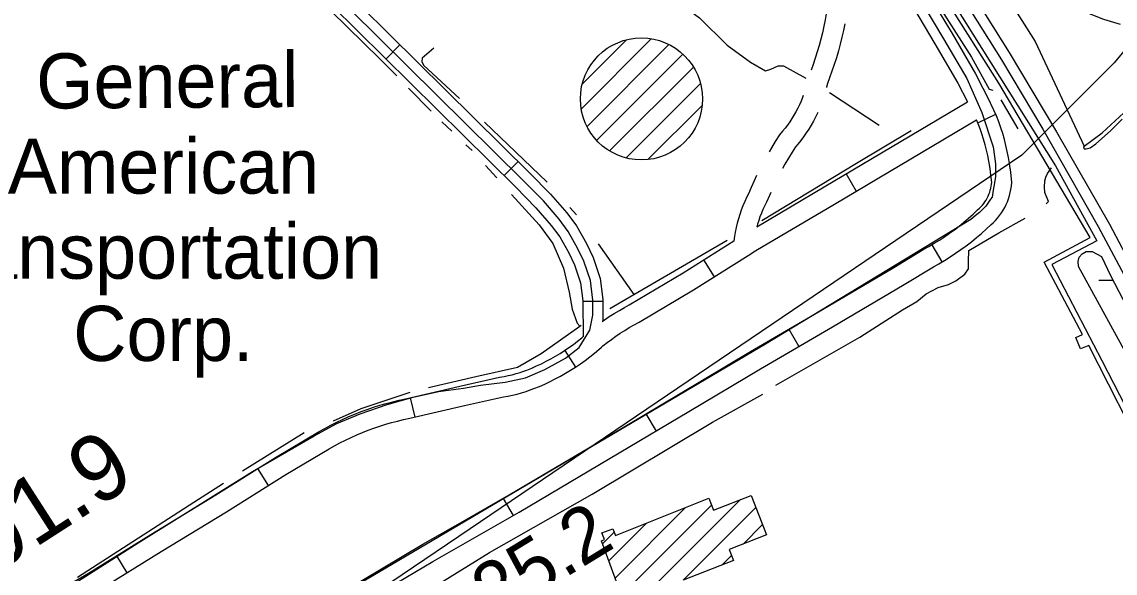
# Model space of a CAD drawing. Extents: x 3568792 to 3606828, y 529143 to 554785.
# Drawn here: x 3577857 to 3579503, y 542432 to 543262 of the extents above; entities that cross this region are included whole.
import ezdxf

# ---------------------------------------------------------------- set-up
doc = ezdxf.new("R2010")
doc.units = 0
for name, color, linetype in [('V-BLDG-IDEN', 7, 'Continuous'), ('V-BLDG-OTLN', 7, 'Continuous'), ('V-DOMW-TANK', 7, 'Continuous'), ('V-RAIL-TRAK', 7, 'Continuous'), ('V-RIVR-RANG-IDEN', 7, 'Continuous'), ('V-ROAD-CNTR', 7, 'Continuous'), ('V-SITE-OTLN', 7, 'Continuous'), ('V-SURV-IDEN', 7, 'Continuous'), ('V-TOPO-SHOR', 7, 'Continuous'), ('V-UTIL-LINE', 7, 'Continuous'), ('V-WETL-SWMP', 7, 'Continuous')]:
    doc.layers.add(name, color=color, linetype=linetype)

msp = doc.modelspace()

# ---------------------------------------------------------------- linework, layer by layer
at = {"layer": 'V-BLDG-OTLN'}
for p, q in [((3578815.2, 542419.2), (3578939.2, 542543.2)), ((3578750.4, 542425.1), (3578856.6, 542531.3)), ((3578759.9, 542399.3), (3578895.7, 542535)), ((3578853.2, 542421.8), (3578962.5, 542531.1)), ((3578741, 542451), (3578797.6, 542507.6)), ((3578731.5, 542476.8), (3578748.9, 542494.3)), ((3578943.1, 542476.3), (3578972.5, 542505.7)), ((3578911.6, 542444.9), (3578925.6, 542458.9))]:
    msp.add_line(p, q, dxfattribs=at)
msp.add_lwpolyline([(3578760.1, 542398.9), (3578729.8, 542481.3), (3578734.5, 542483), (3578730.7, 542493.1), (3578747.1, 542499.2), (3578750.9, 542488.9), (3578891.6, 542545.3), (3578898.8, 542527.3), (3578955.3, 542549.5), (3578978.5, 542490.2), (3578922, 542468.1), (3578928.5, 542451.5), (3578853.1, 542421.8)], dxfattribs=at)
at = {"layer": 'V-DOMW-TANK'}
for p, q in [((3578699.7, 543131.7), (3578804.8, 543236.8)), ((3578701, 543168.4), (3578767.9, 543235.3)), ((3578708.3, 543105), (3578831.5, 543228.2)), ((3578722.9, 543084.2), (3578852.4, 543213.7)), ((3578742.3, 543068.2), (3578868.3, 543194.3)), ((3578767.1, 543057.7), (3578878.9, 543169.5)), ((3578799.7, 543055), (3578881.4, 543136.6))]:
    msp.add_line(p, q, dxfattribs=at)
msp.add_circle((3578790.2, 543146.4), 91.9, dxfattribs=at)
at = {"layer": 'V-RAIL-TRAK'}
for points in [[(3578536.4, 544224.4), (3578627.1, 544129.6), (3578694.9, 544054.9), (3578778.3, 543960.5), (3578866.7, 543856.9), (3578955.1, 543745.6), (3579031.6, 543647.5), (3579088.4, 543571.9), (3579177.7, 543441.8), (3579267.5, 543308.4), (3579332.1, 543205.3), (3579394.4, 543100.9), (3579477.7, 542954.3), (3579574.8, 542772.3)], [(3578565.7, 544214.1), (3578656.6, 544118.2), (3578746.6, 544020.4), (3578839.8, 543911.9), (3578933, 543799.6), (3579019.3, 543688.8), (3579105.3, 543574.3), (3579173.6, 543478.4), (3579272.6, 543330), (3579343.6, 543216.4), (3579415.1, 543096.9), (3579494.7, 542958), (3579566.2, 542822.8)]]:
    msp.add_lwpolyline(points, dxfattribs=at)
at = {"layer": 'V-ROAD-CNTR'}
for p, q in [((3578426.8, 543228.2), (3578405.7, 543206.8)), ((3579296.5, 543110.5), (3579323.5, 543123.5)), ((3578604.5, 543052.4), (3578583.4, 543031)), ((3579098.1, 543033.4), (3579113.5, 543007.6)), ((3579227.3, 542926.9), (3579242.5, 542901)), ((3578883.8, 542903.9), (3578899.8, 542878.6)), ((3578732, 542841.6), (3578702, 542841.4)), ((3579012.1, 542799.8), (3579027.2, 542773.9)), ((3578674.6, 542767.7), (3578690.8, 542742.4)), ((3578442, 542696.6), (3578448.8, 542667.4)), ((3578797, 542672.3), (3578812.2, 542646.4)), ((3578212.3, 542589.9), (3578228.3, 542564.4)), ((3578582, 542545), (3578596.9, 542519)), ((3577999.8, 542458.4), (3578015.5, 542432.9))]:
    msp.add_line(p, q, dxfattribs=at)
for points in [[(3578663.5, 544023.6), (3578672.4, 544020), (3578747.8, 543935.9), (3578841.6, 543826.5), (3578906.9, 543744), (3578989.7, 543635.9), (3579078.1, 543516.5), (3579159.4, 543395.7), (3579225, 543299.6), (3579257.8, 543244.7), (3579293.1, 543184), (3579315.1, 543141)], [(3578025, 543584.3), (3578125.4, 543484), (3578601, 543013.7), (3578631.4, 542982.6), (3578654.5, 542955.9), (3578667.2, 542938.7), (3578680.8, 542914.5), (3578689.6, 542896.4), (3578698.6, 542869.5), (3578701.9, 542842.4), (3578702.3, 542788.2)], [(3577653.3, 542236.7), (3578032.5, 542478.2), (3578204.9, 542585.6), (3578297.7, 542639.2), (3578331.4, 542657.9), (3578366.7, 542672.5), (3578407.5, 542686.3), (3578446.6, 542697.2), (3578484.8, 542705.7), (3578522.2, 542711), (3578547.9, 542715.4), (3578585.2, 542720.2), (3578615.5, 542726.7), (3578644.7, 542739.2), (3578675.7, 542756), (3578696.3, 542772), (3578712.5, 542798.2), (3578717, 542820.9), (3578716.9, 542843.4), (3578713.3, 542872.8), (3578703.6, 542902.1), (3578694.1, 542921.5), (3578679.8, 542946.9), (3578666.2, 542965.3), (3578642.5, 542992.8), (3578611.6, 543024.3), (3578136, 543494.6)], [(3578157.2, 543494.8), (3578622.3, 543034.8), (3578653.5, 543002.9), (3578677.9, 542974.7), (3578692.5, 542955.1), (3578707.4, 542928.5), (3578717.5, 542907.7), (3578728, 542876.1), (3578731.9, 542844.3), (3578732.1, 542812.8)], [(3579140.1, 543370.7), (3579199.8, 543283.4), (3579231.9, 543229.5), (3579266.4, 543170.2), (3579280.8, 543142.1)], [(3579212.4, 543291.5), (3579244.8, 543237.1), (3579279.8, 543177.1), (3579302.7, 543126.1), (3579319.6, 543074.1), (3579323.1, 543048.9), (3579323.2, 543029.6), (3579321.6, 543020.2), (3579319.5, 543008.9), (3579317.9, 542998.6), (3579315.7, 542995.7), (3579308.5, 542984.7), (3579299.3, 542975.5), (3579295.2, 542972.2), (3579286, 542964.9), (3578977, 542777.3), (3578305.2, 542380.6)], [(3579070.4, 543286.6), (3579066.8, 543265.6), (3579064.9, 543255.9), (3579062.7, 543246.1), (3579060.3, 543236.5), (3579057.7, 543226.8), (3579054.9, 543217.2), (3579051.9, 543207.7), (3579048.7, 543198.3), (3579045.6, 543189.9)], [(3579096.2, 543259.5), (3579094.2, 543249.6), (3579091.9, 543239.3), (3579089.3, 543229), (3579086.6, 543218.7), (3579083.6, 543208.5), (3579080.4, 543198.4), (3579077, 543188.3), (3579073.3, 543178.3), (3579070, 543169.6), (3579068.8, 543164.2), (3579068.6, 543163.6)], [(3579033.8, 543151.8), (3579032.6, 543148.6), (3579030.4, 543143.1), (3579028, 543137.7), (3579025.4, 543132.4), (3579022.7, 543127.1), (3579019.7, 543122), (3579016.6, 543116.9), (3579013.4, 543112), (3579010, 543107.1), (3579006.4, 543102.4), (3579002.7, 543097.8), (3578997.9, 543092.3), (3578991.4, 543082.1), (3578985.7, 543072.6), (3578982.2, 543066.6)], [(3578354.3, 542377.6), (3578476.3, 542450), (3578539.6, 542486.2), (3578606.2, 542524.2), (3578756.7, 542613.6), (3578861.5, 542675.6), (3578969.5, 542740.2), (3579077.9, 542803.5), (3579185.6, 542866.9), (3579229.7, 542893.7), (3579237.9, 542898.3), (3579246.4, 542903.3), (3579254.8, 542908.6), (3579263, 542914), (3579271.1, 542919.6), (3579279.1, 542925.4), (3579287, 542931.4), (3579294.7, 542937.7), (3579302.2, 542944), (3579309.6, 542950.6), (3579316.6, 542957.1), (3579319.8, 542960), (3579323.1, 542963.4), (3579326.3, 542967), (3579329.3, 542970.8), (3579332.1, 542974.7), (3579334.7, 542978.8), (3579337.1, 542982.9), (3579339.2, 542987.3), (3579341.1, 542991.7), (3579342.8, 542996.2), (3579344.2, 543000.8), (3579345.4, 543005.4), (3579346.3, 543010.1), (3579347, 543014.9), (3579347.5, 543020.6), (3579346.6, 543030.9), (3579345.5, 543040.1), (3579345.2, 543041.9), (3579344.2, 543049.2), (3579342.6, 543058.3), (3579340.8, 543067.4), (3579338.8, 543076.4), (3579336.5, 543085.3), (3579334, 543094.2), (3579331.2, 543103), (3579328.2, 543111.7), (3579324.8, 543120.8), (3579316.6, 543137.9), (3579315.1, 543141)], [(3578963.8, 542953.7), (3579065.4, 543013.9), (3579280.8, 543142.1)], [(3579055.5, 543125.8), (3579055.2, 543125.1), (3579052.2, 543118.9), (3579049, 543112.8), (3579045.6, 543106.8), (3579042, 543100.9), (3579038.2, 543095.1), (3579034.2, 543089.4), (3579030, 543083.9), (3579025.7, 543078.5), (3579022.1, 543074.3), (3579016.9, 543066.3), (3579011.5, 543057.3), (3579006.2, 543048.2), (3579002.4, 543041.4)], [(3577973.4, 542406.9), (3578067.4, 542464.9), (3578165.4, 542525), (3578254.7, 542581), (3578320, 542619.5), (3578328.1, 542624.1), (3578336.3, 542628.5), (3578344.6, 542632.7), (3578353, 542636.7), (3578361.5, 542640.5), (3578370.1, 542644.1), (3578378.8, 542647.6), (3578387.5, 542650.8), (3578396.3, 542653.8), (3578405.2, 542656.6), (3578414.1, 542659.2), (3578423.1, 542661.5), (3578432.2, 542663.7), (3578441.6, 542665.7), (3578523.7, 542684.9), (3578582.5, 542698), (3578588.9, 542699.1), (3578596, 542700.5), (3578602.9, 542702.1), (3578609.8, 542704), (3578616.7, 542706), (3578620, 542707.2), (3578628.4, 542710.3), (3578636.6, 542713.6), (3578644.6, 542717.1), (3578652.6, 542720.8), (3578660.5, 542724.8), (3578668.3, 542728.9), (3578676, 542733.3), (3578683.5, 542737.8), (3578691, 542742.6), (3578698.3, 542747.5), (3578705.4, 542752.6), (3578712.5, 542758), (3578719.5, 542763.6), (3578726, 542769.3), (3578730.2, 542772.8), (3578732.2, 542774.5), (3578738.5, 542779.6), (3578744.9, 542784.4), (3578751.5, 542789.1), (3578758.2, 542793.7), (3578765, 542798), (3578771.9, 542802.1), (3578779, 542806.1), (3578786.6, 542810.2), (3578868.5, 542858.9), (3578950.8, 542910.7), (3578962.4, 542918.1), (3579080.8, 542988.1), (3579294.3, 543115.1)], [(3578338.9, 542403.4), (3578461.2, 542475.9), (3578524.7, 542512.2), (3578591.1, 542550.2), (3578741.4, 542639.4), (3578846.2, 542701.3), (3578954.2, 542766.1), (3579062.7, 542829.4), (3579170.2, 542892.7), (3579214.5, 542919.6), (3579222.9, 542924.3), (3579230.8, 542929), (3579238.6, 542933.8), (3579246.2, 542938.9), (3579253.8, 542944.1), (3579261.2, 542949.5), (3579268.4, 542955), (3579275.5, 542960.8), (3579282.5, 542966.7), (3579289.4, 542972.8), (3579296.3, 542979.2), (3579299, 542981.7), (3579301.3, 542984), (3579303.4, 542986.4), (3579305.4, 542988.9), (3579307.3, 542991.5), (3579309, 542994.2), (3579310.6, 542997), (3579312, 542999.9), (3579313.3, 543002.8), (3579314.4, 543005.8), (3579315.3, 543008.9), (3579316.1, 543012), (3579316.7, 543015.1), (3579317.2, 543018.3), (3579317.4, 543020.6), (3579316.7, 543027.9), (3579315.7, 543036.2), (3579315.5, 543037.7), (3579314.5, 543044.6), (3579313.1, 543052.9), (3579311.5, 543061.1), (3579309.6, 543069.3), (3579307.5, 543077.5), (3579305.2, 543085.6), (3579302.7, 543093.6), (3579300, 543101.6), (3579297.2, 543109), (3579294.3, 543115.1)], [(3578963.6, 543031.3), (3578959.8, 543023.3), (3578955.3, 543013.1), (3578951.2, 543003.5), (3578948.5, 542998.1), (3578945.6, 542991.9), (3578942.9, 542985.5), (3578940.4, 542979.1), (3578938.2, 542972.6), (3578936.2, 542966), (3578934.4, 542959.4), (3578932.8, 542952.7), (3578931.5, 542946), (3578930.5, 542939.6), (3578929.2, 542932.4)], [(3578984.8, 543005.5), (3578982.8, 543001.2), (3578978.5, 542990.9), (3578975.5, 542985), (3578973, 542979.7), (3578970.7, 542974.3), (3578968.6, 542968.8), (3578966.7, 542963.3), (3578965, 542957.7), (3578964, 542953.9)], [(3578731.2, 542811.5), (3578734.4, 542813.8), (3578741.8, 542818.8), (3578749.3, 542823.5), (3578756.9, 542828.1), (3578764.6, 542832.4), (3578771.9, 542836.3), (3578852.9, 542884.4), (3578929.1, 542932.6)], [(3577880, 542387.1), (3577957.9, 542432.6), (3578051.7, 542490.4), (3578149.6, 542550.5), (3578239.1, 542606.6), (3578305, 542645.5), (3578313.7, 542650.4), (3578322.5, 542655.1), (3578331.4, 542659.7), (3578340.4, 542664), (3578349.6, 542668.1), (3578358.8, 542671.9), (3578368.1, 542675.6), (3578377.5, 542679), (3578387, 542682.3), (3578396.5, 542685.3), (3578406.1, 542688.1), (3578415.8, 542690.6), (3578425.5, 542693), (3578435, 542695), (3578517, 542714.1), (3578576.7, 542727.4), (3578583.4, 542728.6), (3578589.5, 542729.8), (3578595.6, 542731.2), (3578601.7, 542732.9), (3578607.6, 542734.7), (3578610.1, 542735.5), (3578617.5, 542738.2), (3578625, 542741.2), (3578632.3, 542744.4), (3578639.6, 542747.8), (3578646.8, 542751.4), (3578653.9, 542755.2), (3578660.8, 542759.2), (3578667.7, 542763.3), (3578674.5, 542767.6), (3578681.1, 542772.1), (3578687.7, 542776.8), (3578694.1, 542781.6), (3578700.2, 542786.5), (3578702.6, 542788.7)]]:
    msp.add_lwpolyline(points, dxfattribs=at)
at = {"layer": 'V-SITE-OTLN'}
msp.add_lwpolyline([(3579384.2, 545786.4), (3579538.3, 545657), (3579549.8, 545647.4), (3580635.2, 544735.3), (3580116.2, 543943), (3579501.6, 543200.6), (3579362.7, 543061.6), (3579330.4, 543039.8), (3578532.2, 542499.2), (3578292.2, 542336.7), (3578519.2, 542033.8), (3578546.1, 541997.9), (3577753.6, 541531.3), (3577722.7, 541563.5), (3577444.5, 541854.1), (3577305.5, 541999.2), (3577161, 542150.2), (3577019.9, 542441.1), (3576823.4, 542760.8)], dxfattribs=at)
at = {"layer": 'V-TOPO-SHOR'}
for p, q in [((3578439.4, 543162.4), (3578473.8, 543128)), ((3579073.2, 543155.9), (3579147.9, 543106.7)), ((3579331, 543144.8), (3579356.7, 543101.3)), ((3578489.8, 543112), (3578504.5, 543097.8)), ((3578553.8, 543111.2), (3578648.5, 543021)), ((3578526, 543077.1), (3578535.2, 543068.9)), ((3578555.3, 543046.4), (3578572.7, 543027.6)), ((3578682.2, 542983.1), (3578692.3, 542971.7)), ((3578725.1, 542928), (3578778.7, 542851.8)), ((3578189.6, 542586.5), (3578282.6, 542644.2))]:
    msp.add_line(p, q, dxfattribs=at)
for points in [[(3578010.4, 544646), (3578016.8, 544645.5), (3578111.2, 544569.4), (3578256.8, 544442.5), (3578425, 544286.2), (3578572.9, 544137.8), (3578734.2, 543956.8), (3578869.3, 543799.1), (3579043.8, 543571.4), (3579164.7, 543401.4), (3579287, 543209.4), (3579313.6, 543161.3), (3579319.1, 543159.5)], [(3579009.1, 543869.6), (3578995.6, 543854.3), (3578990.7, 543842.1), (3578987.5, 543830.9), (3578987.5, 543817.9), (3578991.6, 543805.7), (3579000.6, 543788.2), (3579029.8, 543749.5), (3579133.7, 543606.4), (3579259.1, 543428.8), (3579382.8, 543233.1), (3579456.8, 543075.1)], [(3579511.5, 543258.2), (3579486.1, 543265.9), (3579435.4, 543285.8), (3579409.6, 543300.3), (3579399.2, 543308), (3579387.9, 543322.5), (3579359.3, 543373.3), (3579291.4, 543476.6), (3579278.7, 543492.4), (3579276, 543497.8), (3579262.4, 543521), (3579222.1, 543577.6), (3579159.6, 543666.4), (3579077.6, 543784.6), (3579057.3, 543817.7), (3579055.4, 543825.4), (3579055, 543831.7), (3579056.8, 543836.7)], [(3578273.6, 543327.8), (3578396.8, 543206.4), (3578422, 543181.2)], [(3578815, 543314.9), (3578877.4, 543268.4), (3578919.3, 543227.4), (3578954.3, 543201.9), (3578977.1, 543188.7), (3578984.9, 543191), (3578995.8, 543196), (3579004, 543196), (3579037.7, 543177.8)], [(3578477.7, 543222.8), (3578460, 543207.8), (3578459.5, 543202.7), (3578462.3, 543197.3), (3578516.5, 543147.2)], [(3579455.6, 543074.3), (3579456.8, 543075.1), (3579483.7, 543095.4), (3579568.3, 543173.6)], [(3579455.6, 543074.3), (3579456.5, 543071.1), (3579459.7, 543071.1), (3579465.7, 543072.9), (3579474, 543078.9), (3579496.1, 543098.6), (3579514, 543116.1)], [(3578971.6, 542963.5), (3579114.1, 543049.6), (3579196.1, 543098.7)], [(3579399.3, 542988.6), (3579402.9, 542991.8), (3579397.4, 543005.5), (3579397, 543013.3), (3579397.4, 543022.9), (3579398.8, 543028.4), (3579401.6, 543033.9), (3579407.5, 543042.6)], [(3578594.7, 543002.4), (3578636.4, 542956.6), (3578657, 542928.7), (3578673, 542891.5), (3578681.3, 542855.4), (3578685.9, 542829.7), (3578693.6, 542808.6), (3578697.2, 542804.1)], [(3578992.4, 542715.6), (3579118.8, 542787.5), (3579183.4, 542828.7), (3579204.5, 542841.5), (3579218.7, 542853), (3579237, 542862.6), (3579252.6, 542867.2), (3579263.6, 542872.7), (3579276.9, 542882.7), (3579282.4, 542890.5), (3579282.4, 542901.5), (3579282.9, 542918), (3579328.2, 542945), (3579367.6, 542967)], [(3578742.5, 542830.7), (3578778.7, 542851.8), (3578919.4, 542933.8)], [(3578469.6, 542712), (3578541.1, 542728.5), (3578603.4, 542742.7), (3578639.1, 542763.3), (3578697.2, 542804.1), (3578699.6, 542805.9)], [(3578326.6, 542661.6), (3578368.3, 542680.4), (3578442.1, 542705.1)], [(3578284, 542297.8), (3578316, 542318.4), (3578339.4, 542328.5), (3578400.8, 542364.2), (3578561.6, 542463.6), (3578716.1, 542551.6), (3578897, 542659.7), (3578972.7, 542701.8)], [(3577941.3, 542426.6), (3578116.3, 542539.3), (3578161.2, 542567.7)]]:
    msp.add_lwpolyline(points, dxfattribs=at)
at = {"layer": 'V-UTIL-LINE'}
for points in [[(3578189.8, 544529.6), (3578228.2, 544498), (3578342.1, 544392.7), (3578565.7, 544169), (3578775.2, 543941.2), (3579032.6, 543621.3), (3579232.5, 543334.8), (3579413.3, 543045.5), (3579475.7, 542932.5), (3579407.8, 542897), (3579483.4, 542752.5), (3579643.2, 542441.4), (3579761.6, 542177.1)], [(3579523, 542658.7), (3579463.8, 542775.3), (3579451.1, 542770.3), (3579444.2, 542787.2), (3579454.2, 542791.7), (3579396.4, 542900.6), (3579465.7, 542937.9), (3579328.1, 543170.3), (3579196.5, 543378.5)]]:
    msp.add_lwpolyline(points, dxfattribs=at)
at = {"layer": 'V-WETL-SWMP'}
msp.add_line((3579478.6, 542873.5), (3579499.8, 542873.6), dxfattribs=at)
msp.add_lwpolyline([(3579724.4, 542342.4), (3579668.8, 542480.5), (3579601.9, 542610.3), (3579534, 542737.4), (3579448, 542894.1), (3579447.5, 542901.4), (3579449.3, 542908.2), (3579453.4, 542913.3), (3579459.8, 542916.9), (3579468.9, 542916.9), (3579482.6, 542909.1), (3579496.2, 542880.4), (3579577.8, 542724.6), (3579707.1, 542482.3), (3579794.5, 542289.1)], dxfattribs=at)

# ---------------------------------------------------------------- texts
at = {"layer": 'V-BLDG-IDEN'}
msp.add_text('General', height=83, rotation=0.3301, dxfattribs=at).set_placement((3577879.2, 543131.8))
for s, p in [('American', (3577836.3, 543003.8)), ('Transportation', (3577684.1, 542875.7)), ('Corp.', (3577934.8, 542751.9))]:
    msp.add_text(s, height=83, dxfattribs=at).set_placement(p)
at = {"layer": 'V-RIVR-RANG-IDEN'}
msp.add_text('R-125.2', height=83, rotation=31.4398, dxfattribs=at).set_placement((3578416.1, 542266.6))
at = {"layer": 'V-SURV-IDEN'}
msp.add_text('5375+01.9', height=100, rotation=32.7606, dxfattribs=at).set_placement((3577497.8, 542225.9))

doc.saveas('drawing.dxf')
